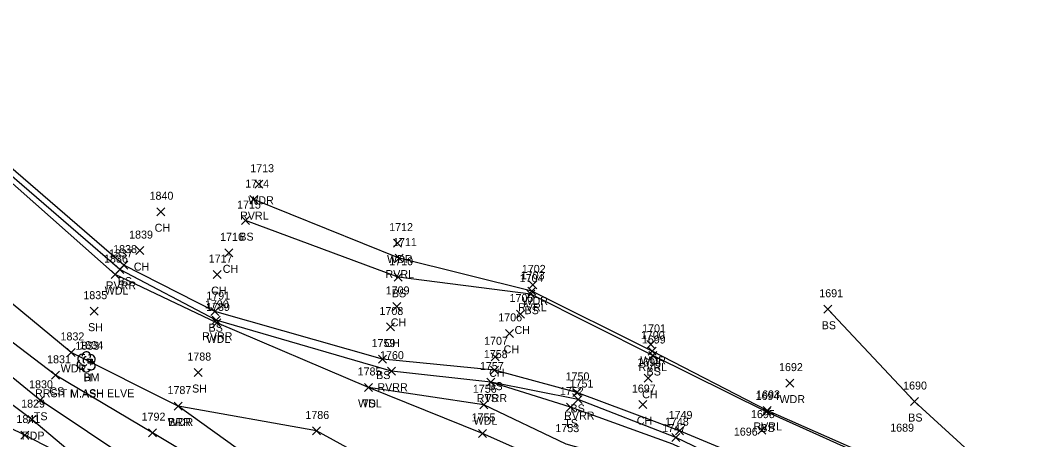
# Model space of a CAD drawing. Extents: x 1537342 to 1542195, y 163002 to 168596.
# Drawn here: x 1541684.3 to 1541938.8, y 163409.7 to 163514.4 of the extents above; entities that cross this region are included whole.
import ezdxf

# ---------------------------------------------------------------- set-up
doc = ezdxf.new("R2010")
doc.units = 0
for name, color, linetype in [('C_A', 7, 'Continuous'), ('C_C', 7, 'Continuous'), ('C_I', 7, 'Continuous'), ('CPBM', 7, 'Continuous'), ('L_A', 7, 'Continuous'), ('L_C', 7, 'Continuous'), ('L_I', 7, 'Continuous'), ('L_TIC', 7, 'Continuous'), ('LABL', 7, 'Continuous'), ('LAWA', 7, 'Continuous'), ('LAWE', 7, 'Continuous'), ('LELB', 7, 'Continuous'), ('LTD', 7, 'Continuous'), ('P_A', 7, 'Continuous'), ('P_I', 7, 'Continuous'), ('P_TIC', 7, 'Continuous'), ('PET', 7, 'Continuous')]:
    doc.layers.add(name, color=color, linetype=linetype)

msp = doc.modelspace()

# ---------------------------------------------------------------- linework, layer by layer
at = {"layer": 'CPBM'}
for p, q in [((1541701.26, 163428.76), (1541701.26, 163429.76)), ((1541701.26, 163429.76), (1541702.26, 163429.76)), ((1541702.26, 163428.76), (1541701.26, 163428.76)), ((1541701.76, 163429.26), (1541701.76, 163429.26)), ((1541701.76, 163429.26), (1541701.76, 163429.26)), ((1541702.26, 163429.76), (1541702.26, 163428.76))]:
    msp.add_line(p, q, dxfattribs=at)
at = {"layer": 'L_TIC'}
for points in [[(1541742.9, 163472.49), (1541744.9, 163474.49)], [(1541744.9, 163472.49), (1541742.9, 163474.49)], [(1541741.66, 163468.64), (1541743.66, 163470.64)], [(1541743.66, 163468.64), (1541741.66, 163470.64)], [(1541718.39, 163465.61), (1541720.39, 163467.61)], [(1541720.39, 163465.61), (1541718.39, 163467.61)], [(1541739.6, 163463.39), (1541741.6, 163465.39)], [(1541741.6, 163463.39), (1541739.6, 163465.39)], [(1541777.61, 163457.76), (1541779.61, 163459.76)], [(1541779.61, 163457.76), (1541777.61, 163459.76)], [(1541713.2, 163455.9), (1541715.2, 163457.9)], [(1541715.2, 163455.9), (1541713.2, 163457.9)], [(1541735.42, 163455.34), (1541737.42, 163457.34)], [(1541737.42, 163455.34), (1541735.42, 163457.34)], [(1541709.21, 163452.27), (1541711.21, 163454.27)], [(1541711.21, 163452.27), (1541709.21, 163454.27)], [(1541778.01, 163454.02), (1541780.01, 163456.02)], [(1541780.01, 163454.02), (1541778.01, 163456.02)], [(1541706.98, 163449.9), (1541708.98, 163451.9)], [(1541708.98, 163449.9), (1541706.98, 163451.9)], [(1541708.17, 163451.19), (1541710.17, 163453.19)], [(1541710.17, 163451.19), (1541708.17, 163453.19)], [(1541732.52, 163449.9), (1541734.52, 163451.9)], [(1541734.52, 163449.9), (1541732.52, 163451.9)], [(1541777.73, 163449.23), (1541779.73, 163451.23)], [(1541779.73, 163449.23), (1541777.73, 163451.23)], [(1541811.42, 163447.32), (1541813.42, 163449.32)], [(1541813.42, 163447.32), (1541811.42, 163449.32)], [(1541810.88, 163445.01), (1541812.88, 163447.01)], [(1541812.88, 163445.01), (1541810.88, 163447.01)], [(1541811.16, 163445.74), (1541813.16, 163447.74)], [(1541813.16, 163445.74), (1541811.16, 163447.74)], [(1541777.41, 163441.95), (1541779.41, 163443.95)], [(1541779.41, 163441.95), (1541777.41, 163443.95)], [(1541701.75, 163440.76), (1541703.75, 163442.76)], [(1541703.75, 163440.76), (1541701.75, 163442.76)], [(1541731.91, 163440.64), (1541733.91, 163442.64)], [(1541733.91, 163440.64), (1541731.91, 163442.64)], [(1541808.34, 163440.05), (1541810.34, 163442.05)], [(1541810.34, 163440.05), (1541808.34, 163442.05)], [(1541885.16, 163441.24), (1541887.16, 163443.24)], [(1541887.16, 163441.24), (1541885.16, 163443.24)], [(1541732.23, 163438.48), (1541734.23, 163440.48)], [(1541734.23, 163438.48), (1541732.23, 163440.48)], [(1541732.43, 163437.83), (1541734.43, 163439.83)], [(1541734.43, 163437.83), (1541732.43, 163439.83)], [(1541775.84, 163436.81), (1541777.84, 163438.81)], [(1541777.84, 163436.81), (1541775.84, 163438.81)], [(1541805.6, 163435.21), (1541807.6, 163437.21)], [(1541807.6, 163435.21), (1541805.6, 163437.21)], [(1541840.92, 163432.46), (1541842.92, 163434.46)], [(1541842.92, 163432.46), (1541840.92, 163434.46)], [(1541696.04, 163430.45), (1541698.04, 163432.45)], [(1541698.04, 163430.45), (1541696.04, 163432.45)], [(1541801.99, 163429.35), (1541803.99, 163431.35)], [(1541803.99, 163429.35), (1541801.99, 163431.35)], [(1541841.26, 163430.79), (1541843.26, 163432.79)], [(1541843.26, 163430.79), (1541841.26, 163432.79)], [(1541841.39, 163429.68), (1541843.39, 163431.68)], [(1541843.39, 163429.68), (1541841.39, 163431.68)], [(1541773.79, 163428.79), (1541775.79, 163430.79)], [(1541775.79, 163428.79), (1541773.79, 163430.79)], [(1541692.13, 163424.74), (1541694.13, 163426.74)], [(1541694.13, 163424.74), (1541692.13, 163426.74)], [(1541727.75, 163425.42), (1541729.75, 163427.42)], [(1541729.75, 163425.42), (1541727.75, 163427.42)], [(1541776.04, 163425.76), (1541778.04, 163427.76)], [(1541778.04, 163425.76), (1541776.04, 163427.76)], [(1541801.85, 163426.02), (1541803.85, 163428.02)], [(1541803.85, 163426.02), (1541801.85, 163428.02)], [(1541840.24, 163423.99), (1541842.24, 163425.99)], [(1541842.24, 163423.99), (1541840.24, 163425.99)], [(1541770.31, 163421.69), (1541772.31, 163423.69)], [(1541772.31, 163421.69), (1541770.31, 163423.69)], [(1541770.31, 163421.69), (1541772.31, 163423.69)], [(1541772.31, 163421.69), (1541770.31, 163423.69)], [(1541800.87, 163423.04), (1541802.87, 163425.04)], [(1541802.87, 163423.04), (1541800.87, 163425.04)], [(1541800.87, 163423.04), (1541802.87, 163425.04)], [(1541802.87, 163423.04), (1541800.87, 163425.04)], [(1541875.67, 163422.78), (1541877.67, 163424.78)], [(1541877.67, 163422.78), (1541875.67, 163424.78)], [(1541822.37, 163420.46), (1541824.37, 163422.46)], [(1541824.37, 163420.46), (1541822.37, 163422.46)], [(1541822.72, 163418.67), (1541824.72, 163420.67)], [(1541824.72, 163418.67), (1541822.72, 163420.67)], [(1541688.28, 163418.49), (1541690.28, 163420.49)], [(1541690.28, 163418.49), (1541688.28, 163420.49)], [(1541722.78, 163417.04), (1541724.78, 163419.04)], [(1541724.78, 163417.04), (1541722.78, 163419.04)], [(1541722.78, 163417.04), (1541724.78, 163419.04)], [(1541724.78, 163417.04), (1541722.78, 163419.04)], [(1541799.16, 163417.36), (1541801.16, 163419.36)], [(1541801.16, 163417.36), (1541799.16, 163419.36)], [(1541820.84, 163416.77), (1541822.84, 163418.77)], [(1541822.84, 163416.77), (1541820.84, 163418.77)], [(1541838.89, 163417.42), (1541840.89, 163419.42)], [(1541840.89, 163417.42), (1541838.89, 163419.42)], [(1541906.78, 163418.17), (1541908.78, 163420.17)], [(1541908.78, 163418.17), (1541906.78, 163420.17)], [(1541869.81, 163415.57), (1541871.81, 163417.57)], [(1541871.81, 163415.57), (1541869.81, 163417.57)], [(1541869.95, 163415.96), (1541871.95, 163417.96)], [(1541871.95, 163415.96), (1541869.95, 163417.96)], [(1541868.66, 163411.03), (1541870.66, 163413.03)], [(1541870.66, 163411.03), (1541868.66, 163413.03)], [(1541716.31, 163410.39), (1541718.31, 163412.39)], [(1541718.31, 163410.39), (1541716.31, 163412.39)], [(1541757.29, 163410.82), (1541759.29, 163412.82)], [(1541759.29, 163410.82), (1541757.29, 163412.82)], [(1541798.78, 163410.2), (1541800.78, 163412.2)], [(1541800.78, 163410.2), (1541798.78, 163412.2)], [(1541847.11, 163409.16), (1541849.11, 163411.16)], [(1541849.11, 163409.16), (1541847.11, 163411.16)], [(1541848.05, 163410.83), (1541850.05, 163412.83)], [(1541850.05, 163410.83), (1541848.05, 163412.83)]]:
    msp.add_lwpolyline(points, dxfattribs=at)
at = {"layer": 'LABL'}
msp.add_lwpolyline([(1541844.34, 163370.6), (1541821.33, 163359.44), (1541813.12, 163355.49), (1541797.38, 163365.13), (1541723.78, 163418.04)], dxfattribs=at)
at = {"layer": 'LAWA'}
for points in [[(1541858.3, 163366.25), (1541851.23, 163367.97), (1541844.34, 163370.6), (1541815.36, 163382.31), (1541797.41, 163395.47), (1541778.64, 163400.7), (1541758.29, 163411.82), (1541723.78, 163418.04), (1541697.04, 163431.45), (1541651.96, 163468.67), (1541626.15, 163491.84), (1541623.99, 163498.52), (1541617.66, 163502.86), (1541594.18, 163514.44)], [(1541858.3, 163366.25), (1541879.51, 163370.15), (1541893.62, 163370.51), (1541908.1, 163373.66), (1541889.78, 163380.93), (1541869.01, 163392.19), (1541846.9, 163401.17), (1541820.74, 163408.53), (1541800.16, 163418.36), (1541771.31, 163422.69), (1541733.43, 163438.83), (1541707.98, 163450.9), (1541667.55, 163486.78), (1541634.88, 163501.17)]]:
    msp.add_lwpolyline(points, dxfattribs=at)
at = {"layer": 'LAWE'}
for points in [[(1541807.79, 163344.41), (1541817.37, 163345.92), (1541838.27, 163351.14), (1541849.61, 163357.05), (1541859.07, 163364.08), (1541878.93, 163368.69), (1541894.03, 163369.19), (1541909.94, 163373.2), (1541909.62, 163375.47), (1541892.25, 163384.66), (1541871.9, 163398.76), (1541848.11, 163410.16), (1541823.72, 163419.67), (1541801.87, 163424.04), (1541777.04, 163426.76), (1541733.23, 163439.48), (1541709.17, 163452.19), (1541667.42, 163488.13), (1541636.18, 163502.23)], [(1541964.97, 163374.84), (1541943.31, 163378.43), (1541921.03, 163388.83), (1541900.78, 163403.75), (1541870.95, 163416.96), (1541842.26, 163431.79), (1541812.16, 163446.74), (1541779.01, 163455.02), (1541742.66, 163469.64)]]:
    msp.add_lwpolyline(points, dxfattribs=at)
at = {"layer": 'LELB'}
for points in [[(1541806.46, 163346.35), (1541770.85, 163375.53), (1541766.11, 163382.32), (1541753.11, 163384.46), (1541712.96, 163403.65), (1541689.28, 163419.49), (1541645.56, 163455.19), (1541611.14, 163481.6), (1541585.04, 163504.65)], [(1541813.12, 163355.49), (1541807.59, 163352.29), (1541792.75, 163363.67), (1541773.45, 163377.86), (1541766.85, 163384.06), (1541755.11, 163388.66), (1541717.31, 163411.39), (1541693.13, 163425.74), (1541646.55, 163461.21), (1541615.06, 163486.33), (1541589.07, 163507.09)], [(1541872.66, 163402.01), (1541849.05, 163411.83), (1541823.37, 163421.46), (1541802.85, 163427.02), (1541774.79, 163429.79), (1541732.91, 163441.64), (1541710.21, 163453.27), (1541668.38, 163489.32)], [(1541964.73, 163370.11), (1541945.07, 163376.64), (1541920.27, 163388.01), (1541900.01, 163403.43), (1541870.81, 163416.57), (1541842.39, 163430.68), (1541811.88, 163446.01), (1541778.73, 163450.23), (1541740.6, 163464.39)], [(1541943.1, 163382.66), (1541929.91, 163398.91), (1541907.78, 163419.17), (1541886.16, 163442.24)], [(1541908.1, 163373.66), (1541890.7, 163382.73), (1541871.8, 163397.05), (1541847.41, 163408.55), (1541821.84, 163417.77), (1541801.87, 163424.04)], [(1541844.34, 163370.6), (1541854.93, 163375.48), (1541838.12, 163386.11), (1541819.72, 163402.38), (1541799.78, 163411.2), (1541771.31, 163422.69)]]:
    msp.add_lwpolyline(points, dxfattribs=at)
at = {"layer": 'LTD'}
msp.add_line((1541700.76, 163429.12), (1541700.76, 163429.12), dxfattribs=at)
msp.add_line((1541700.76, 163429.12), (1541700.76, 163429.12), dxfattribs=at)
msp.add_arc((1541700.8, 163430.56), 1.05, 335.5272, 180.9563, dxfattribs=at)
for centre, major_axis, ratio, start_param, end_param in [((1541699.97, 163429.79), (1.21, -0.51), 0.895232, 1.570796, 4.712389), ((1541701.8, 163429.71), (-1.14, -0.48), 0.949671, 1.570796, 4.712389), ((1541699.67, 163428.42), (0.58, -1.04), 0.959034, 3.141593, 6.283185), ((1541700.3, 163428.37), (-0.625, -0.083), 0.423636, 0, 3.141593), ((1541700.55, 163429.58), (-0.208, -0.792), 0.645439, 3.141593, 6.283185), ((1541701.26, 163428.96), (-0.5, 0.667), 0.989748, 3.141593, 6.283185), ((1541701.76, 163428.29), (-1.09, 0.79), 0.841452, 1.570796, 4.712389), ((1541700.76, 163427.62), (0.26, 1.06), 0.942809, 1.570796, 4.712389)]:
    msp.add_ellipse(centre, major_axis=major_axis, ratio=ratio, start_param=start_param, end_param=end_param, dxfattribs=at)
at = {"layer": 'P_TIC'}
for points in [[(1541686.22, 163413.66), (1541688.22, 163415.66)], [(1541688.22, 163413.66), (1541686.22, 163415.66)], [(1541684.47, 163409.81), (1541686.47, 163411.81)], [(1541686.47, 163409.81), (1541684.47, 163411.81)]]:
    msp.add_lwpolyline(points, dxfattribs=at)
at = {"layer": 'PET'}
for points in [[(1541702.01, 163402.19), (1541687.22, 163414.66), (1541642.2, 163448.26), (1541608.31, 163479.46), (1541580.56, 163501.03)], [(1541804.88, 163343.94), (1541781.94, 163357.9), (1541762.27, 163369.13), (1541719.07, 163393.38), (1541702.01, 163402.19), (1541685.47, 163410.81), (1541633.42, 163436.22), (1541598.66, 163451.94), (1541573.75, 163461.19), (1541557.97, 163467.97)]]:
    msp.add_lwpolyline(points, dxfattribs=at)

# ---------------------------------------------------------------- texts
at = {"layer": 'C_A'}
msp.add_text('BM', height=2, dxfattribs=at).set_placement((1541700.08, 163424.26))
at = {"layer": 'C_C'}
msp.add_text('RRSIT M.ASH ELVE', height=2, dxfattribs=at).set_placement((1541687.98, 163420.26))
at = {"layer": 'C_I'}
msp.add_text('1834', height=2, dxfattribs=at).set_placement((1541699.07, 163432.26))
at = {"layer": 'L_A'}
for s, p in [('WDR', (1541741.26, 163468.49)), ('RVRL', (1541739.23, 163464.64)), ('CH', (1541717.88, 163461.61)), ('BS', (1541739.04, 163459.39)), ('CH', (1541712.68, 163451.9)), ('WDR', (1541775.97, 163453.76)), ('CH', (1541734.91, 163451.34)), ('RVRL', (1541775.57, 163450.02)), ('RVRR', (1541705.68, 163447.19)), ('BS', (1541708.65, 163448.27)), ('WDL', (1541705.4, 163445.9)), ('CH', (1541732.01, 163445.9)), ('BS', (1541777.17, 163445.23)), ('RVRL', (1541808.73, 163441.74)), ('WDR', (1541809.79, 163443.32)), ('BS', (1541810.32, 163441.01)), ('SH', (1541701.24, 163436.76)), ('BS', (1541731.35, 163436.64)), ('CH', (1541776.9, 163437.95)), ('BS', (1541884.6, 163437.24)), ('RVRR', (1541729.74, 163434.48)), ('CH', (1541807.83, 163436.05)), ('WDL', (1541730.85, 163433.83)), ('CH', (1541775.33, 163432.81)), ('CH', (1541805.09, 163431.21)), ('WDR', (1541694.4, 163426.45)), ('RVRL', (1541838.82, 163426.79)), ('WDR', (1541839.28, 163428.46)), ('H', (1541700.19, 163424.12)), ('BS', (1541773.24, 163424.79)), ('CH', (1541801.48, 163425.35)), ('BS', (1541840.83, 163425.68)), ('SH', (1541727.24, 163421.42)), ('RVRR', (1541773.55, 163421.76)), ('BS', (1541801.29, 163422.02)), ('CS', (1541691.57, 163420.74)), ('RVRR', (1541798.38, 163419.04)), ('TS', (1541800.28, 163419.04)), ('CH', (1541839.72, 163419.99)), ('WDR', (1541874.04, 163418.78)), ('WDL', (1541768.72, 163417.69)), ('TS', (1541769.72, 163417.69)), ('BS', (1541821.81, 163416.46)), ('TS', (1541687.69, 163414.49)), ('RVRR', (1541820.23, 163414.67)), ('BS', (1541906.22, 163414.17)), ('WDR', (1541721.14, 163413.04)), ('BRR', (1541721.27, 163413.04)), ('WDL', (1541797.58, 163413.36)), ('TS', (1541820.25, 163412.77)), ('CH', (1541838.38, 163413.42)), ('RVRL', (1541867.52, 163411.96)), ('BS', (1541869.25, 163411.57))]:
    msp.add_text(s, height=2, dxfattribs=at).set_placement(p)
at = {"layer": 'L_C'}
msp.add_text('M.ASH', height=2, dxfattribs=at).set_placement((1541696.71, 163420.12))
at = {"layer": 'L_I'}
for s, p in [('1713', (1541741.77, 163476.49)), ('1714', (1541740.53, 163472.64)), ('1840', (1541716.61, 163469.61)), ('1715', (1541738.47, 163467.39)), ('1839', (1541711.5, 163459.9)), ('1716', (1541734.24, 163459.34)), ('1712', (1541776.49, 163461.76)), ('1711', (1541777.45, 163458.02)), ('1837', (1541706.47, 163455.19)), ('1838', (1541707.51, 163456.27)), ('1836', (1541705.23, 163453.9)), ('1717', (1541731.39, 163453.9)), ('1710', (1541776.52, 163453.23)), ('1703', (1541809.39, 163449.74)), ('1702', (1541809.65, 163451.32)), ('1704', (1541809.11, 163449.01)), ('1835', (1541700.06, 163444.76)), ('1791', (1541730.78, 163444.64)), ('1709', (1541775.63, 163445.95)), ('1705', (1541806.57, 163444.05)), ('1691', (1541883.99, 163445.24)), ('1790', (1541730.45, 163442.48)), ('1789', (1541730.73, 163441.83)), ('1708', (1541774.07, 163440.81)), ('1706', (1541803.77, 163439.21)), ('1701', (1541839.72, 163436.46)), ('1832', (1541694.35, 163434.45)), ('1700', (1541839.4, 163434.79)), ('1833', (1541698.06, 163432.12)), ('1759', (1541772.09, 163432.79)), ('1707', (1541800.22, 163433.35)), ('1699', (1541839.65, 163433.68)), ('1788', (1541726.06, 163429.42)), ('1760', (1541774.21, 163429.76)), ('1758', (1541800.15, 163430.02)), ('1831', (1541691, 163428.74)), ('1757', (1541799.17, 163427.04)), ('1757', (1541799.17, 163427.04)), ('1698', (1541838.5, 163427.99)), ('1692', (1541873.93, 163426.78)), ('1785', (1541768.61, 163425.69)), ('1785', (1541768.61, 163425.69)), ('1750', (1541820.59, 163424.46)), ('1830', (1541686.5, 163422.49)), ('1756', (1541797.41, 163421.36)), ('1751', (1541821.59, 163422.67)), ('1697', (1541837.15, 163421.42)), ('1690', (1541904.95, 163422.17)), ('1787', (1541721.09, 163421.04)), ('1787', (1541721.09, 163421.04)), ('1752', (1541819.15, 163420.77)), ('1694', (1541868.07, 163419.57)), ('1693', (1541868.21, 163419.96)), ('1792', (1541714.62, 163414.39)), ('1786', (1541755.55, 163414.82)), ('1755', (1541797.09, 163414.2)), ('1749', (1541846.35, 163414.83)), ('1695', (1541866.92, 163415.03)), ('1753', (1541818.04, 163411.53)), ('1753', (1541818.04, 163411.53)), ('1747', (1541844.72, 163411.55)), ('1748', (1541845.42, 163413.16)), ('1689', (1541901.72, 163411.64)), ('1696', (1541862.64, 163410.65))]:
    msp.add_text(s, height=2, dxfattribs=at).set_placement(p)
at = {"layer": 'P_A'}
msp.add_text('RDP', height=2, dxfattribs=at).set_placement((1541684.7, 163409.66))
at = {"layer": 'P_I'}
for s, p in [('1829', (1541684.52, 163417.66)), ('1841', (1541683.34, 163413.81))]:
    msp.add_text(s, height=2, dxfattribs=at).set_placement(p)

doc.saveas('drawing.dxf')
